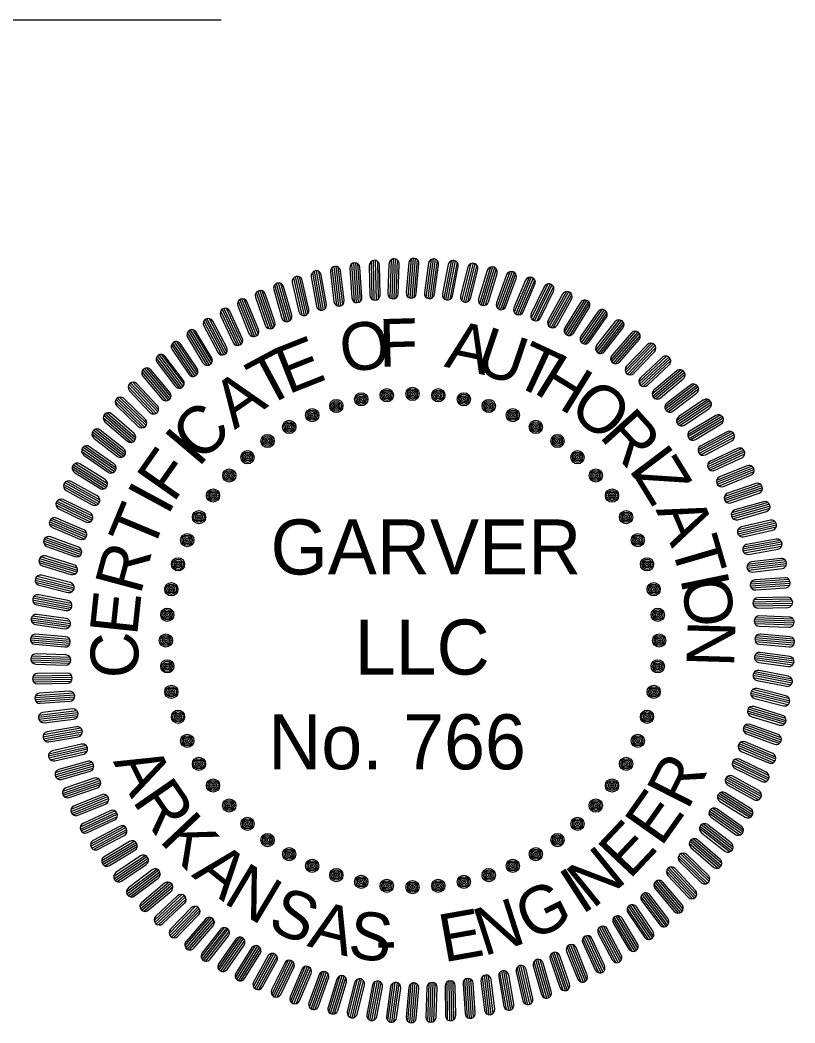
# Model space of a CAD drawing. Extents: x 1212896 to 1368412, y 378476 to 478763.
# Drawn here: x 1340509 to 1352480, y 379535 to 395024 of the extents above; entities that cross this region are included whole.
import ezdxf

# ---------------------------------------------------------------- set-up
doc = ezdxf.new("R2010")
doc.units = 0
doc.layers.add('G-ANNO-TEXT', color=7, linetype='Continuous')
doc.layers.add('R_Draft', color=7, linetype='Continuous')

# ---------------------------------------------------------------- blocks, each defined once
blk = doc.blocks.new('SEALDO')
at = {"layer": 'G-ANNO-TEXT'}
for radius in [0.0396, 0.0305, 0.0213, 0.0122, 0.00305]:
    blk.add_circle((1.403, -0.4559), radius, dxfattribs=at)
blk = doc.blocks.new('SEALRI')
at = {"layer": 'G-ANNO-TEXT'}
for p, q in [((-0.0083, 2.2815), (-0.0281, 2.0555)), ((0.0043, 2.2859), (-0.0164, 2.049)), ((0.0164, 2.2848), (-0.0043, 2.0479)), ((-0.0226, 2.2583), (-0.0381, 2.0809)), ((0.0281, 2.2783), (0.0083, 2.0523)), ((0.0226, 2.0756), (0.0381, 2.253))]:
    blk.add_line(p, q, dxfattribs=at)
for centre, start, end in [((0.0078, 2.2556), 355, 175), ((-0.0078, 2.0782), 175, 355)]:
    blk.add_arc(centre, 0.0305, start, end, dxfattribs=at)

msp = doc.modelspace()

# ---------------------------------------------------------------- linework, layer by layer
at = {"layer": 'R_Draft'}
msp.add_line((1343616, 395024), (1324691, 395024), dxfattribs=at)

# ---------------------------------------------------------------- block references
at = {"layer": 'G-ANNO-TEXT'}
for name, xscale, yscale, rotation in [('SEALRI', 2582.154835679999, 2582.154835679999, 9.000000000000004), ('SEALRI', 2582.15483568, 2582.1548356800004, 6.000000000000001), ('SEALRI', 2582.1548356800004, 2582.1548356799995, 3.0000000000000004), ('SEALRI', 2582.1548356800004, 2582.1548356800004, -2.999999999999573), ('SEALRI', 2582.1548356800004, 2582.1548356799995, -5.999999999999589), ('SEALRI', 2582.15483568, 2582.15483568, -8.999999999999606), ('SEALRI', 2582.15483568, 2582.154835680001, 15.000000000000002), ('SEALRI', 2582.1548356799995, 2582.15483568, 12.000000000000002), ('SEALRI', 2582.1548356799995, 2582.154835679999, -11.999999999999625), ('SEALRI', 2582.15483568, 2582.1548356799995, -14.99999999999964), ('SEALRI', 2582.15483568, 2582.15483568, 20.99999999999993), ('SEALRI', 2582.154835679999, 2582.154835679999, 18.000000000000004), ('SEALRI', 2582.1548356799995, 2582.1548356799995, -17.999999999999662), ('SEALRI', 2582.1548356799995, 2582.15483568, -20.999999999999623), ('SEALRI', 2582.15483568, 2582.15483568, 23.999999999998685), ('SEALRI', 2582.15483568, 2582.15483568, -23.999999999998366), ('SEALRI', 2582.1548356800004, 2582.15483568, 26.999999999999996), ('SEALRI', 2582.15483568, 2582.1548356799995, -26.99999999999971), ('SEALRI', 2582.15483568, 2582.15483568, 30.000000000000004), ('SEALRI', 2582.15483568, 2582.1548356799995, -29.999999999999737), ('SEALRI', 2582.15483568, 2582.1548356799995, 33), ('SEALRI', 2582.1548356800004, 2582.15483568, -32.999999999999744), ('SEALRI', 2582.1548356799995, 2582.15483568, 36), ('SEALRI', 2582.15483568, 2582.1548356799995, -35.999999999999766), ('SEALRI', 2582.1548356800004, 2582.1548356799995, 38.99999999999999), ('SEALRI', 2582.154835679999, 2582.15483568, -38.99999999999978), ('SEALRI', 2582.1548356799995, 2582.15483568, 41.99999999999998), ('SEALRI', 2582.15483568, 2582.15483568, -41.99999999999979), ('SEALRI', 2582.1548356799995, 2582.15483568, 44.99999999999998), ('SEALRI', 2582.1548356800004, 2582.15483568, -44.9999999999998), ('SEALRI', 2582.15483568, 2582.15483568, 48), ('SEALRI', 2582.15483568, 2582.15483568, -47.99999999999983), ('SEALDO', 2582.154835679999, 2582.15483568, 119.99999999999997), ('SEALDO', 2582.1548356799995, 2582.15483568, 113.99999999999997), ('SEALDO', 2582.15483568, 2582.15483568, 107.99999999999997), ('SEALDO', 2582.1548356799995, 2582.15483568, 101.99999999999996), ('SEALDO', 2582.15483568, 2582.15483568, 95.99999999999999), ('SEALRI', 2582.15483568, 2582.1548356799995, 50.99999999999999), ('SEALDO', 2582.15483568, 2582.15483568, 125.99999999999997), ('SEALDO', 2582.15483568, 2582.15483568, 90), ('SEALRI', 2582.15483568, 2582.1548356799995, -50.99999999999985), ('SEALRI', 2582.1548356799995, 2582.15483568, 54.00000000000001), ('SEALDO', 2582.15483568, 2582.15483568, 131.99999999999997), ('SEALDO', 2582.15483568, 2582.1548356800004, 83.99999999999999), ('SEALRI', 2582.15483568, 2582.1548356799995, -53.99999999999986), ('SEALDO', 2582.15483568, 2582.1548356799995, 138), ('SEALDO', 2582.1548356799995, 2582.15483568, 77.99999999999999), ('SEALRI', 2582.15483568, 2582.1548356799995, 56.999999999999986), ('SEALDO', 2582.15483568, 2582.1548356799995, 144), ('SEALDO', 2582.154835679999, 2582.1548356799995, 72), ('SEALRI', 2582.1548356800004, 2582.1548356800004, -56.999999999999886), ('SEALRI', 2582.1548356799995, 2582.15483568, 59.999999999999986), ('SEALDO', 2582.15483568, 2582.1548356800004, 150), ('SEALDO', 2582.15483568, 2582.1548356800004, 66.00000000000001), ('SEALRI', 2582.1548356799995, 2582.1548356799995, -59.99999999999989), ('SEALRI', 2582.1548356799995, 2582.1548356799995, 63), ('SEALRI', 2582.15483568, 2582.1548356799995, -62.99999999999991), ('SEALDO', 2582.15483568, 2582.15483568, 156.00000000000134), ('SEALDO', 2582.15483568, 2582.1548356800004, 60.00000000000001), ('SEALRI', 2582.15483568, 2582.1548356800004, 65.99999999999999), ('SEALRI', 2582.1548356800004, 2582.15483568, -65.99999999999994), ('SEALDO', 2582.1548356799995, 2582.15483568, 162.00000000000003), ('SEALDO', 2582.1548356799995, 2582.15483568, 54.00000000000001), ('SEALRI', 2582.1548356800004, 2582.15483568, 68.99999999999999), ('SEALRI', 2582.15483568, 2582.1548356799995, -68.99999999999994), ('SEALDO', 2582.154835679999, 2582.15483568, 168.00000000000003), ('SEALDO', 2582.15483568, 2582.15483568, 48.00000000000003), ('SEALRI', 2582.154835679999, 2582.1548356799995, 72), ('SEALRI', 2582.1548356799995, 2582.15483568, -71.99999999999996), ('SEALDO', 2582.15483568, 2582.15483568, 174.00000000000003), ('SEALDO', 2582.15483568, 2582.15483568, 42.00000000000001), ('SEALRI', 2582.15483568, 2582.15483568, 75.00000000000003), ('SEALRI', 2582.15483568, 2582.15483568, -74.99999999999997), ('SEALRI', 2582.1548356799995, 2582.15483568, 78.00000000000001), ('SEALDO', 2582.15483568, 2582.15483568, -179.99999999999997), ('SEALDO', 2582.1548356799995, 2582.15483568, 36), ('SEALRI', 2582.1548356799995, 2582.15483568, -78), ('SEALRI', 2582.1548356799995, 2582.1548356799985, 81), ('SEALDO', 2582.154835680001, 2582.15483568, -173.99999999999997), ('SEALDO', 2582.15483568, 2582.1548356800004, 29.999999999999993), ('SEALRI', 2582.154835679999, 2582.154835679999, -81.00000000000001), ('SEALRI', 2582.15483568, 2582.1548356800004, 84.00000000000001), ('SEALRI', 2582.15483568, 2582.15483568, -84.00000000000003), ('SEALRI', 2582.15483568, 2582.1548356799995, 87.00000000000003), ('SEALDO', 2582.15483568, 2582.1548356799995, -167.99999999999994), ('SEALDO', 2582.15483568, 2582.15483568, 23.999999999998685), ('SEALRI', 2582.15483568, 2582.1548356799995, -87.00000000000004), ('SEALRI', 2582.15483568, 2582.15483568, 90.00000000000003), ('SEALDO', 2582.1548356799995, 2582.1548356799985, -161.9999999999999), ('SEALDO', 2582.154835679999, 2582.154835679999, 18.000000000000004), ('SEALRI', 2582.15483568, 2582.15483568, -90.00000000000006), ('SEALRI', 2582.1548356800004, 2582.1548356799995, 93), ('SEALRI', 2582.1548356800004, 2582.15483568, -93.00000000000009), ('SEALDO', 2582.15483568, 2582.15483568, -156.00000000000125), ('SEALDO', 2582.1548356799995, 2582.15483568, 12.000000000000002), ('SEALRI', 2582.15483568, 2582.154835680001, 96.00000000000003), ('SEALRI', 2582.15483568, 2582.1548356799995, -96.0000000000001), ('SEALDO', 2582.15483568, 2582.15483568, -149.99999999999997), ('SEALRI', 2582.1548356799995, 2582.1548356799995, 99.00000000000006), ('SEALDO', 2582.15483568, 2582.1548356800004, 6.000000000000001), ('SEALRI', 2582.15483568, 2582.1548356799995, -99.00000000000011), ('SEALRI', 2582.15483568, 2582.1548356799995, 102.00000000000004), ('SEALDO', 2582.1548356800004, 2582.1548356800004, -143.99999999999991), ('SEALRI', 2582.15483568, 2582.15483568, -102.00000000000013), ('SEALRI', 2582.15483568, 2582.15483568, 105.00000000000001), ('SEALRI', 2582.1548356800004, 2582.15483568, -105.00000000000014), ('SEALDO', 2582.15483568, 2582.15483568, -137.9999999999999), ('SEALDO', 2582.15483568, 2582.15483568, -6.000000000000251), ('SEALRI', 2582.1548356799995, 2582.15483568, 108.00000000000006), ('SEALRI', 2582.1548356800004, 2582.1548356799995, -108.00000000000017), ('SEALDO', 2582.15483568, 2582.1548356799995, -131.99999999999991), ('SEALRI', 2582.15483568, 2582.1548356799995, 111.00000000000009), ('SEALDO', 2582.1548356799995, 2582.15483568, -12.000000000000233), ('SEALRI', 2582.1548356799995, 2582.15483568, -111.00000000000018), ('SEALRI', 2582.1548356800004, 2582.1548356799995, 114.00000000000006), ('SEALRI', 2582.15483568, 2582.1548356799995, -114.0000000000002), ('SEALDO', 2582.15483568, 2582.1548356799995, -125.9999999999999), ('SEALDO', 2582.1548356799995, 2582.1548356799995, -18.00000000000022), ('SEALRI', 2582.15483568, 2582.1548356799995, 117.00000000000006), ('SEALRI', 2582.1548356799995, 2582.1548356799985, -117.00000000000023), ('SEALDO', 2582.154835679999, 2582.1548356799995, -119.99999999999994), ('SEALDO', 2582.15483568, 2582.1548356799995, -23.999999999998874), ('SEALRI', 2582.154835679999, 2582.1548356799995, 120.00000000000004), ('SEALDO', 2582.1548356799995, 2582.1548356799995, -30.00000000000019), ('SEALRI', 2582.15483568, 2582.15483568, -120.00000000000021), ('SEALRI', 2582.15483568, 2582.1548356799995, 123.00000000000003), ('SEALDO', 2582.15483568, 2582.154835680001, -113.99999999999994), ('SEALRI', 2582.15483568, 2582.1548356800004, -123.00000000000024), ('SEALDO', 2582.15483568, 2582.1548356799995, -107.99999999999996), ('SEALDO', 2582.15483568, 2582.15483568, -36.00000000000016), ('SEALRI', 2582.1548356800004, 2582.1548356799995, 126.00000000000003), ('SEALDO', 2582.1548356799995, 2582.15483568, -42.000000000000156), ('SEALRI', 2582.15483568, 2582.1548356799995, -126.00000000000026), ('SEALRI', 2582.15483568, 2582.1548356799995, 129.00000000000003), ('SEALDO', 2582.1548356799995, 2582.1548356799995, -101.99999999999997), ('SEALRI', 2582.1548356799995, 2582.1548356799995, -129.00000000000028), ('SEALRI', 2582.15483568, 2582.1548356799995, 132), ('SEALDO', 2582.15483568, 2582.1548356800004, -96), ('SEALDO', 2582.15483568, 2582.1548356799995, -48.00000000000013), ('SEALRI', 2582.15483568, 2582.1548356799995, -132.00000000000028), ('SEALDO', 2582.15483568, 2582.15483568, -90.00000000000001), ('SEALDO', 2582.15483568, 2582.15483568, -84.00000000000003), ('SEALDO', 2582.15483568, 2582.1548356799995, -60.0000000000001), ('SEALDO', 2582.1548356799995, 2582.1548356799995, -54.00000000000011), ('SEALRI', 2582.154835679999, 2582.154835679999, 135), ('SEALDO', 2582.1548356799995, 2582.15483568, -78.00000000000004), ('SEALDO', 2582.15483568, 2582.1548356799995, -72.00000000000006), ('SEALDO', 2582.1548356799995, 2582.1548356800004, -66.00000000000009), ('SEALRI', 2582.1548356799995, 2582.15483568, -135.00000000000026), ('SEALRI', 2582.15483568, 2582.1548356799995, 138), ('SEALRI', 2582.15483568, 2582.1548356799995, -138.00000000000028), ('SEALRI', 2582.15483568, 2582.1548356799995, 140.99999999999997), ('SEALRI', 2582.154835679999, 2582.15483568, -141.0000000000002), ('SEALRI', 2582.15483568, 2582.1548356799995, 144), ('SEALRI', 2582.15483568, 2582.1548356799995, -144.00000000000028), ('SEALRI', 2582.1548356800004, 2582.15483568, 146.99999999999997), ('SEALRI', 2582.1548356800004, 2582.15483568, -147.00000000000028), ('SEALRI', 2582.15483568, 2582.1548356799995, 149.99999999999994), ('SEALRI', 2582.15483568, 2582.1548356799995, -150.00000000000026), ('SEALRI', 2582.1548356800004, 2582.1548356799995, 152.99999999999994), ('SEALRI', 2582.15483568, 2582.1548356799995, -153.0000000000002), ('SEALRI', 2582.15483568, 2582.1548356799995, 156.00000000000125), ('SEALRI', 2582.15483568, 2582.15483568, -156.00000000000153), ('SEALRI', 2582.15483568, 2582.1548356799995, 159), ('SEALRI', 2582.1548356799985, 2582.1548356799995, 161.99999999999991), ('SEALRI', 2582.1548356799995, 2582.15483568, -162.00000000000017), ('SEALRI', 2582.15483568, 2582.1548356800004, -159.00000000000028), ('SEALRI', 2582.154835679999, 2582.15483568, 164.99999999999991), ('SEALRI', 2582.15483568, 2582.1548356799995, 167.99999999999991), ('SEALRI', 2582.15483568, 2582.15483568, -168.0000000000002), ('SEALRI', 2582.1548356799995, 2582.1548356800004, -165.00000000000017), ('SEALRI', 2582.15483568, 2582.1548356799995, 170.9999999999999), ('SEALRI', 2582.15483568, 2582.1548356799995, 173.9999999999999), ('SEALRI', 2582.1548356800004, 2582.15483568, 176.9999999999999), ('SEALRI', 2582.15483568, 2582.15483568, 179.99999999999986), ('SEALRI', 2582.1548356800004, 2582.15483568, -177.00000000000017), ('SEALRI', 2582.1548356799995, 2582.1548356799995, -174.00000000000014), ('SEALRI', 2582.1548356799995, 2582.15483568, -171.00000000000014)]:
    msp.add_blockref(name, (1346572, 385441), dxfattribs=dict(at, xscale=xscale, yscale=yscale, rotation=rotation))
at = {"layer": 'G-ANNO-TEXT', "xscale": 2582.15483568, "yscale": 2582.15483568}
for name in ['SEALRI', 'SEALDO']:
    msp.add_blockref(name, (1346572, 385441), dxfattribs=at)

# ---------------------------------------------------------------- texts
at = {"layer": 'G-ANNO-TEXT'}
for s, rotation, p in [('O', 8.2771, (1345503, 389571)), ('F', 1.6104, (1346063, 389667)), ('A', 348.2771, (1347049, 389673)), ('U', 341.2772, (1347510, 389600)), ('E', 21.6104, (1344649, 389238)), ('T', 334.9438, (1348090, 389412)), ('T', 28.2771, (1344292, 389030)), ('H', 328.2771, (1348422, 389281)), ('A', 34.9438, (1343823, 388690)), ('O', 319.7874, (1348956, 388978)), ('C', 44.3881, (1343300, 388170)), ('R', 311.9933, (1349440, 388592)), ('I', 49.7408, (1343262, 388095)), ('F', 54.9438, (1342878, 387554)), ('I', 307.0081, (1349890, 388086)), ('Z', 301.6104, (1349977, 387997)), ('I', 61.6104, (1342790, 387355)), ('T', 67.4314, (1342542, 386783)), ('A', 292.9752, (1350325, 387461)), ('T', 286.3085, (1350556, 386927)), ('R', 74.9438, (1342369, 386133)), ('I', 281.6104, (1350704, 386408)), ('O', 276.4823, (1350732, 386381)), ('E', 83.8985, (1342316, 385502)), ('C', 91.8842, (1342349, 384873)), ('N', 268.2771, (1350824, 385759)), ('A', 296.5747, (1341940, 383572)), ('R', 63.0959, (1350823, 382806)), ('R', 304.6183, (1342231, 382965)), ('E', 54.7309, (1350413, 382240)), ('K', 313.3805, (1342645, 382347)), ('E', 46.6807, (1349924, 381736)), ('A', 321.2584, (1343144, 381808)), ('N', 38.9821, (1349354, 381285)), ('N', 329.1099, (1343629, 381400)), ('I', 32.979, (1349183, 381198)), ('G', 26.4132, (1348399, 380786)), ('S', 337.6294, (1344310, 380985)), ('A', 345.4073, (1344931, 380724)), ('N', 17.8686, (1347673, 380561)), ('S', 352.8046, (1345557, 380548)), ('E', 10.0695, (1347055, 380469)), ('-', 0.8385, (1346003, 380452))]:
    msp.add_text(s, height=738, rotation=rotation, dxfattribs=at).set_placement(p)
for s, p in [('GARVER', (1344379, 386461)), ('LLC', (1345679, 384915)), ('No. 766', (1344342, 383452))]:
    msp.add_text(s, height=850, dxfattribs=at).set_placement(p)

doc.saveas('drawing.dxf')
